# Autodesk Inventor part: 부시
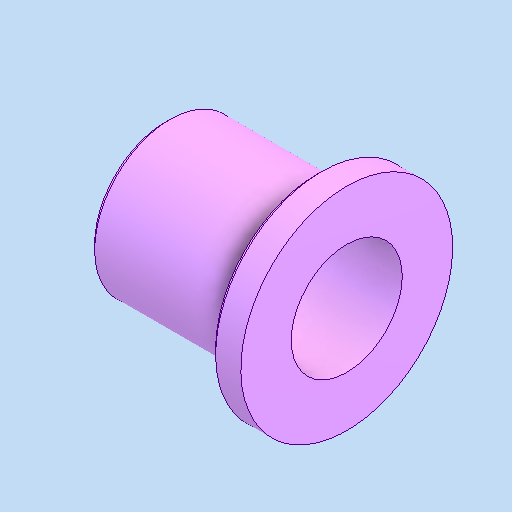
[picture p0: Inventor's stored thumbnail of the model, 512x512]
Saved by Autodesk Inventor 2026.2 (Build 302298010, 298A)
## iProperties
Created: 2026-08
Part Number: 부시
Material: 강철, 연강
Document SubType Name: Modeling
Designer: PC2-02
Density: 7.86 g/cm^3
Appearance: 기본값
Author: jhkim
Sending System: Autodesk Inventor 2027
Preprocessor: ST-DEVELOPER v20.1
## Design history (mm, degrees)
feature "솔리드1"
node "솔리드2"
